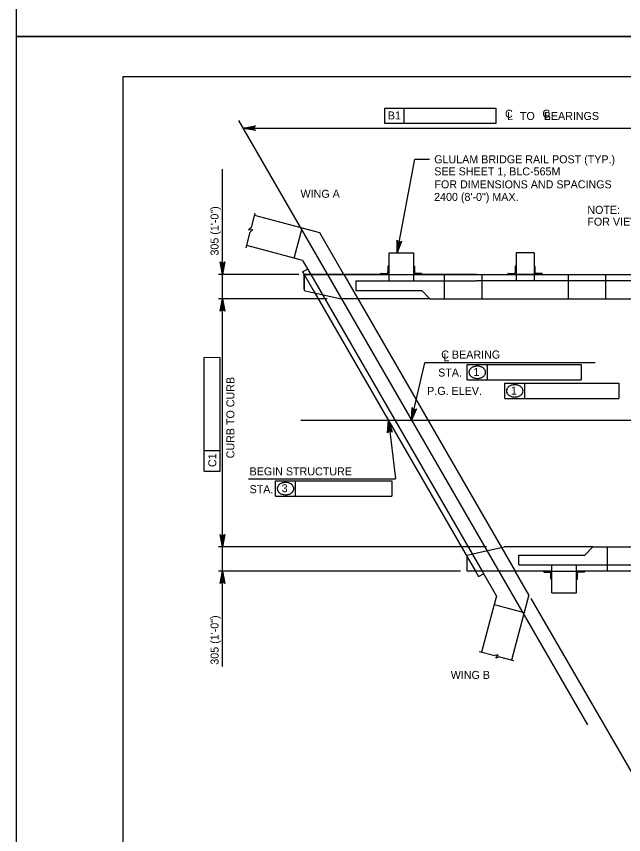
# Model space of a CAD drawing. Extents: x 638175 to 640495, y 294277 to 298435.
# Drawn here: x 638435.5 to 638663, y 296948.4 to 297255 of the extents above; entities that cross this region are included whole.
import ezdxf

# ---------------------------------------------------------------- set-up
doc = ezdxf.new("R2010")
doc.units = 0
for name, color, linetype in [('2', 7, 'Continuous'), ('3', 7, 'Continuous'), ('4', 7, 'Continuous'), ('PLT-BNDY', 7, 'Continuous')]:
    doc.layers.add(name, color=color, linetype=linetype)

msp = doc.modelspace()

# ---------------------------------------------------------------- linework, layer by layer
at = {"layer": '2'}
for p, q in [((638475.46, 296668.46), (638475.46, 297232.46)), ((638475.46, 297232.46), (639261.46, 297232.46)), ((638549.18, 297173.84), (638524.78, 297180.38)), ((638539.56, 297164.37), (638542.57, 297175.61)), ((638558.17, 297158.27), (638549.18, 297173.84)), ((638539.56, 297164.37), (638521.77, 297169.14)), ((638575.02, 297166.36), (638584.25, 297166.36)), ((638575.02, 297166.36), (638575.02, 297155.88)), ((638584.25, 297166.36), (638584.25, 297155.88)), ((638629.41, 297166.36), (638622.68, 297166.36)), ((638629.41, 297166.36), (638622.68, 297166.36)), ((638622.68, 297166.36), (638622.68, 297155.88)), ((638629.41, 297166.36), (638629.41, 297155.88)), ((638542.71, 297163.52), (638539.56, 297164.37)), ((638542.71, 297163.52), (638545.74, 297158.27)), ((638542.73, 297159.22), (638544.58, 297160.29)), ((638542.73, 297159.22), (638544.58, 297160.29)), ((638574.65, 297161.18), (638574.65, 297159)), ((638574.83, 297161.36), (638575.02, 297161.36)), ((638575.02, 297161.36), (638575.02, 297158.27)), ((638584.43, 297161.36), (638584.25, 297161.36)), ((638584.25, 297161.36), (638584.25, 297158.27)), ((638584.62, 297161.18), (638584.62, 297159)), ((638622.32, 297161.18), (638622.32, 297159)), ((638622.5, 297161.36), (638622.68, 297161.36)), ((638622.68, 297161.36), (638622.68, 297158.27)), ((638629.59, 297161.36), (638629.41, 297161.36)), ((638629.41, 297161.36), (638629.41, 297158.27)), ((638629.77, 297161.18), (638629.77, 297159)), ((638542.73, 297159.22), (638543.27, 297158.29)), ((638543.27, 297158.27), (638755.15, 297158.27)), ((638543.27, 297152.89), (638543.27, 297158.27)), ((638543.27, 297158.27), (638543.27, 297152.24)), ((638575.02, 297158.27), (638543.27, 297158.27)), ((638543.28, 297158.27), (638547.02, 297151.79)), ((638545.74, 297158.27), (638609.93, 297047.1)), ((638558.17, 297158.27), (638622.36, 297047.1)), ((638571.92, 297158.45), (638571.92, 297158.27)), ((638575.02, 297158.27), (638571.92, 297158.27)), ((638572.11, 297158.63), (638574.29, 297158.63)), ((638575.02, 297158.27), (638584.25, 297158.27)), ((638584.25, 297158.27), (638587.34, 297158.27)), ((638607.96, 297158.27), (638584.25, 297158.27)), ((638587.16, 297158.63), (638584.98, 297158.63)), ((638587.34, 297158.45), (638587.34, 297158.27)), ((638595.8, 297158.27), (638595.8, 297149.15)), ((638608.04, 297158.27), (638755.13, 297158.27)), ((638609.87, 297158.27), (638609.87, 297149.15)), ((638619.59, 297158.45), (638619.59, 297158.27)), ((638622.68, 297158.27), (638619.59, 297158.27)), ((638619.77, 297158.63), (638621.95, 297158.63)), ((638630.66, 297158.27), (638621.42, 297158.27)), ((638629.41, 297158.27), (638622.68, 297158.27)), ((638629.41, 297158.27), (638632.5, 297158.27)), ((638632.32, 297158.63), (638630.13, 297158.63)), ((638632.5, 297158.45), (638632.5, 297158.27)), ((638642.21, 297158.27), (638642.21, 297149.15)), ((638656.24, 297158.27), (638656.24, 297149.15)), ((638562.69, 297155.88), (638607.87, 297155.88)), ((638562.69, 297155.88), (638562.69, 297152.24)), ((638735.71, 297155.88), (638607.87, 297155.88)), ((638543.27, 297152.24), (638545.44, 297151.76)), ((638545.44, 297151.76), (638557.12, 297149.15)), ((638547.03, 297151.77), (638604.35, 297052.5)), ((638562.69, 297152.24), (638587.33, 297152.24)), ((638590.42, 297149.15), (638587.33, 297152.24)), ((638590.42, 297149.15), (638557.12, 297149.15)), ((638590.42, 297149.15), (638606.58, 297149.15)), ((638590.42, 297149.15), (638741.28, 297149.15)), ((638606.53, 297053.61), (638618.21, 297056.22)), ((638651.51, 297056.22), (638618.21, 297056.22)), ((638651.51, 297056.22), (638648.42, 297053.13)), ((638651.51, 297056.22), (638667.67, 297056.22)), ((638651.51, 297056.22), (638802.37, 297056.22)), ((638656.89, 297047.1), (638656.89, 297056.22)), ((638604.36, 297053.13), (638606.53, 297053.61)), ((638604.36, 297047.1), (638604.36, 297053.13)), ((638623.78, 297049.49), (638623.78, 297053.13)), ((638623.78, 297053.13), (638648.42, 297053.13)), ((638604.36, 297052.48), (638607.47, 297047.1)), ((638636.11, 297047.1), (638604.36, 297047.1)), ((638607.47, 297047.1), (638608.64, 297045.07)), ((638609.93, 297047.1), (638615.33, 297037.75)), ((638627.5, 297038.19), (638622.36, 297047.1)), ((638627.5, 297038.19), (638622.36, 297047.1)), ((638623.78, 297049.49), (638668.96, 297049.49)), ((638633.01, 297046.92), (638633.01, 297047.1)), ((638636.1, 297047.1), (638633.01, 297047.1)), ((638633.2, 297046.73), (638635.38, 297046.73)), ((638636.1, 297044.01), (638636.1, 297047.1)), ((638636.11, 297039.01), (638636.11, 297049.49)), ((638636.11, 297047.1), (638645.34, 297047.1)), ((638645.34, 297039.01), (638645.34, 297049.49)), ((638645.34, 297047.1), (638648.43, 297047.1)), ((638645.34, 297044.01), (638645.34, 297047.1)), ((638669.05, 297047.1), (638645.34, 297047.1)), ((638648.25, 297046.73), (638646.07, 297046.73)), ((638648.43, 297046.92), (638648.43, 297047.1)), ((638608.64, 297045.07), (638610.48, 297046.14)), ((638635.74, 297044.19), (638635.74, 297046.37)), ((638635.92, 297044.01), (638636.1, 297044.01)), ((638645.52, 297044.01), (638645.34, 297044.01)), ((638645.71, 297044.19), (638645.71, 297046.37)), ((638615.33, 297037.75), (638614.48, 297034.59)), ((638627.5, 297038.19), (638620.96, 297013.79)), ((638636.11, 297039.01), (638645.34, 297039.01)), ((638614.48, 297034.59), (638609.72, 297016.8)), ((638614.48, 297034.59), (638625.73, 297031.58))]:
    msp.add_line(p, q, dxfattribs=at)
for centre, radius, start, end in [((638574.83, 297161.18), 0.182, 90, 179.9984), ((638584.43, 297161.18), 0.182, 0.0016, 90), ((638622.5, 297161.18), 0.182, 90, 179.9984), ((638629.59, 297161.18), 0.182, 0.0016, 90), ((638572.11, 297158.45), 0.182, 90, 179.9984), ((638574.29, 297159), 0.364, 270, 359.9984), ((638584.98, 297159), 0.364, 180.0016, 270), ((638587.16, 297158.45), 0.182, 0.0016, 90), ((638619.77, 297158.45), 0.182, 90, 179.9984), ((638621.95, 297159), 0.364, 270, 359.9984), ((638630.13, 297159), 0.364, 180.0016, 270), ((638632.32, 297158.45), 0.182, 0.0016, 90), ((638633.2, 297046.92), 0.182, 180.0016, 270), ((638635.38, 297046.37), 0.364, 0.0016, 90), ((638646.07, 297046.37), 0.364, 90, 179.9984), ((638648.25, 297046.92), 0.182, 270, 359.9984), ((638635.92, 297044.19), 0.182, 180.0016, 270), ((638645.52, 297044.19), 0.182, 270, 359.9984)]:
    msp.add_arc(centre, radius, start, end, dxfattribs=at)
at = {"layer": '3'}
for p, q in [((638518.64, 297215.98), (638649.42, 296989.47)), ((638520.34, 297213.03), (638711.75, 297213.03)), ((638584.73, 297201.51), (638590.25, 297201.51)), ((638523.56, 297175.84), (638524.99, 297181.17)), ((638523.56, 297175.84), (638522.47, 297175.02)), ((638521.53, 297168.26), (638523.1, 297174.1)), ((638522.47, 297175.02), (638524.03, 297175.11)), ((638524.03, 297175.11), (638523.1, 297174.1)), ((638608.85, 297017.03), (638614.68, 297015.47)), ((638616.02, 297015.77), (638614.68, 297015.47)), ((638615.16, 297014.47), (638616.02, 297015.77)), ((638616.42, 297015.01), (638615.16, 297014.47)), ((638616.42, 297015.01), (638621.75, 297013.58))]:
    msp.add_line(p, q, dxfattribs=at)
msp.add_lwpolyline([(638523.29, 297213.52), (638523.29, 297212.54), (638520.34, 297213.03)], close=True, dxfattribs=at)
at = {"layer": '4'}
for p, q in [((638573.56, 297220.57), (638580.79, 297220.57)), ((638573.56, 297214.81), (638573.56, 297220.57)), ((638580.79, 297214.81), (638580.79, 297220.57)), ((638580.79, 297220.57), (638615.09, 297220.57)), ((638615.09, 297220.57), (638615.09, 297214.81)), ((638615.09, 297214.81), (638573.56, 297214.81)), ((638578.11, 297166.36), (638584.73, 297201.51)), ((638512.67, 297011.33), (638512.67, 297197.76)), ((638541.29, 297158.27), (638511.23, 297158.27)), ((638551.87, 297149.15), (638511.23, 297149.15)), ((638511.77, 297127.08), (638505.86, 297127.09)), ((638505.86, 297092.13), (638505.86, 297127.09)), ((638511.77, 297084.56), (638511.77, 297127.08)), ((638583.5, 297103.64), (638588.55, 297125.15)), ((638652.37, 297125.15), (638588.55, 297125.15)), ((638604.38, 297124.53), (638611.95, 297124.53)), ((638604.38, 297118.76), (638604.38, 297124.53)), ((638611.95, 297118.76), (638611.95, 297124.53)), ((638611.95, 297124.53), (638647.14, 297124.53)), ((638647.14, 297124.53), (638647.14, 297118.76)), ((638604.38, 297118.76), (638647.14, 297118.76)), ((638618.42, 297117.56), (638625.99, 297117.56)), ((638618.42, 297111.8), (638618.42, 297117.56)), ((638625.99, 297111.8), (638625.99, 297117.56)), ((638625.99, 297117.56), (638661.18, 297117.56)), ((638661.18, 297117.56), (638661.18, 297111.8)), ((638618.42, 297111.8), (638661.18, 297111.8)), ((638541.99, 297103.64), (638827.01, 297103.64)), ((638574.83, 297103.64), (638577.55, 297081.71)), ((638505.86, 297084.57), (638505.86, 297092.13)), ((638511.77, 297092.13), (638505.86, 297092.13)), ((638505.86, 297084.57), (638511.77, 297084.56)), ((638522.47, 297081.71), (638577.55, 297081.71)), ((638532.53, 297075.18), (638532.53, 297080.94)), ((638532.53, 297080.94), (638540.1, 297080.94)), ((638540.1, 297075.18), (638540.1, 297080.94)), ((638540.1, 297080.94), (638576.11, 297080.94)), ((638576.11, 297080.94), (638576.11, 297075.18)), ((638532.53, 297075.18), (638576.11, 297075.18)), ((638611.65, 297056.22), (638511.23, 297056.22)), ((638601.88, 297047.1), (638511.23, 297047.1)), ((638628.28, 297036.84), (638675.2, 296955.57))]:
    msp.add_line(p, q, dxfattribs=at)
for points in [[(638520.34, 297213.03), (638525, 297213.9), (638524.64, 297213.65), (638524.46, 297213.34), (638524.4, 297213.03), (638524.46, 297212.72), (638524.64, 297212.4), (638525, 297212.16), (638520.34, 297213.03), (638524.64, 297212.4), (638524.46, 297212.72), (638520.34, 297213.03), (638524.4, 297213.03), (638524.46, 297213.34), (638520.34, 297213.03), (638524.64, 297213.65)], [(638578.11, 297166.36), (638578.09, 297171.1), (638578.27, 297170.71), (638578.54, 297170.47), (638578.84, 297170.36), (638579.16, 297170.35), (638579.5, 297170.48), (638579.81, 297170.79), (638578.11, 297166.36), (638579.5, 297170.48), (638579.16, 297170.35), (638578.11, 297166.36), (638578.84, 297170.36), (638578.54, 297170.47), (638578.11, 297166.36), (638578.27, 297170.71)], [(638512.67, 297158.27), (638511.8, 297162.93), (638512.05, 297162.57), (638512.36, 297162.39), (638512.67, 297162.33), (638512.99, 297162.39), (638513.3, 297162.57), (638513.55, 297162.93), (638512.67, 297158.27), (638513.3, 297162.57), (638512.99, 297162.39), (638512.67, 297158.27), (638512.67, 297162.33), (638512.36, 297162.39), (638512.67, 297158.27), (638512.05, 297162.57)], [(638512.67, 297149.15), (638513.55, 297144.49), (638513.3, 297144.85), (638512.99, 297145.03), (638512.67, 297145.09), (638512.36, 297145.03), (638512.05, 297144.85), (638511.8, 297144.49), (638512.67, 297149.15), (638512.05, 297144.85), (638512.36, 297145.03), (638512.67, 297149.15), (638512.67, 297145.09), (638512.99, 297145.03), (638512.67, 297149.15), (638513.3, 297144.85)], [(638583.5, 297103.64), (638583.72, 297108.37), (638583.88, 297107.97), (638584.14, 297107.72), (638584.43, 297107.59), (638584.74, 297107.57), (638585.09, 297107.68), (638585.42, 297107.97), (638583.5, 297103.64), (638585.09, 297107.68), (638584.74, 297107.57), (638583.5, 297103.64), (638584.43, 297107.59), (638584.14, 297107.72), (638583.5, 297103.64), (638583.88, 297107.97)], [(638574.83, 297103.64), (638576.27, 297099.12), (638575.98, 297099.45), (638575.64, 297099.59), (638575.33, 297099.61), (638575.02, 297099.51), (638574.74, 297099.29), (638574.53, 297098.9), (638574.83, 297103.64), (638574.74, 297099.29), (638575.02, 297099.51), (638574.83, 297103.64), (638575.33, 297099.61), (638575.64, 297099.59), (638574.83, 297103.64), (638575.98, 297099.45)], [(638512.67, 297056.22), (638511.8, 297060.88), (638512.05, 297060.52), (638512.36, 297060.34), (638512.67, 297060.28), (638512.99, 297060.34), (638513.3, 297060.52), (638513.55, 297060.88), (638512.67, 297056.22), (638513.3, 297060.52), (638512.99, 297060.34), (638512.67, 297056.22), (638512.67, 297060.28), (638512.36, 297060.34), (638512.67, 297056.22), (638512.05, 297060.52)], [(638512.67, 297047.1), (638513.55, 297042.43), (638513.3, 297042.79), (638512.99, 297042.98), (638512.67, 297043.03), (638512.36, 297042.98), (638512.05, 297042.79), (638511.8, 297042.43), (638512.67, 297047.1), (638512.05, 297042.79), (638512.36, 297042.98), (638512.67, 297047.1), (638512.67, 297043.03), (638512.99, 297042.98), (638512.67, 297047.1), (638513.3, 297042.79)]]:
    msp.add_lwpolyline(points, dxfattribs=at)
for points in [[(638578.15, 297169.36), (638579.12, 297169.18), (638578.11, 297166.36)], [(638512.19, 297161.15), (638513.15, 297161.15), (638512.67, 297158.27)], [(638512.19, 297146.27), (638513.15, 297146.27), (638512.67, 297149.15)], [(638512.19, 297059.1), (638513.15, 297059.1), (638512.67, 297056.22)], [(638512.19, 297044.21), (638513.15, 297044.21), (638512.67, 297047.1)]]:
    msp.add_lwpolyline(points, close=True, dxfattribs=at)
for centre, radius, start, end in [((638607.43, 297121.22), 2.49, 126.3544, 150.6308), ((638607.87, 297120.62), 3.23, 106.9552, 126.3544), ((638608.16, 297119.67), 4.22, 90, 106.9552), ((638608.16, 297119.67), 4.22, 73.0448, 90), ((638608.45, 297120.62), 3.23, 53.6456, 73.0448), ((638608.89, 297121.22), 2.49, 29.3692, 53.6456), ((638606.75, 297121.6), 1.71, 150.6308, 180), ((638606.75, 297121.6), 1.71, 180, 209.3692), ((638607.43, 297121.98), 2.49, 209.3692, 233.6456), ((638608.89, 297121.98), 2.49, 306.3544, 330.6308), ((638609.57, 297121.6), 1.71, 0, 29.3692), ((638609.57, 297121.6), 1.71, 330.6308, 0), ((638607.87, 297122.58), 3.23, 233.6456, 253.0448), ((638608.16, 297123.53), 4.22, 253.0448, 270), ((638608.16, 297123.53), 4.22, 270, 286.9552), ((638608.45, 297122.58), 3.23, 286.9552, 306.3544), ((638620.79, 297114.63), 1.71, 150.6308, 180), ((638620.79, 297114.63), 1.71, 180, 209.3692), ((638621.47, 297114.25), 2.49, 126.3544, 150.6308), ((638621.91, 297113.65), 3.23, 106.9552, 126.3544), ((638622.2, 297112.71), 4.22, 90, 106.9552), ((638622.2, 297112.71), 4.22, 73.0448, 90), ((638622.49, 297113.65), 3.23, 53.6456, 73.0448), ((638622.93, 297114.25), 2.49, 29.3692, 53.6456), ((638623.61, 297114.63), 1.71, 0, 29.3692), ((638623.61, 297114.63), 1.71, 330.6308, 0), ((638621.47, 297115.01), 2.49, 209.3692, 233.6456), ((638621.91, 297115.61), 3.23, 233.6456, 253.0448), ((638622.2, 297116.56), 4.22, 253.0448, 270), ((638622.2, 297116.56), 4.22, 270, 286.9552), ((638622.49, 297115.61), 3.23, 286.9552, 306.3544), ((638622.93, 297115.01), 2.49, 306.3544, 330.6308), ((638536.31, 297076.09), 4.22, 90, 106.9552), ((638536.31, 297076.09), 4.22, 73.0448, 90), ((638534.9, 297078.01), 1.71, 150.6308, 180), ((638534.9, 297078.01), 1.71, 180, 209.3692), ((638535.58, 297077.63), 2.49, 126.3544, 150.6308), ((638535.58, 297078.39), 2.49, 209.3692, 233.6456), ((638536.02, 297077.03), 3.23, 106.9552, 126.3544), ((638536.6, 297077.03), 3.23, 53.6456, 73.0448), ((638537.04, 297077.63), 2.49, 29.3692, 53.6456), ((638537.04, 297078.39), 2.49, 306.3544, 330.6308), ((638537.71, 297078.01), 1.71, 0, 29.3692), ((638537.71, 297078.01), 1.71, 330.6308, 0), ((638536.02, 297078.99), 3.23, 233.6456, 253.0448), ((638536.31, 297079.94), 4.22, 253.0448, 270), ((638536.31, 297079.94), 4.22, 270, 286.9552), ((638536.6, 297078.99), 3.23, 286.9552, 306.3544)]:
    msp.add_arc(centre, radius, start, end, dxfattribs=at)
at = {"layer": 'PLT-BNDY'}
for points in [[(638435.46, 297841.46), (639276.46, 297841.46), (639276.46, 297247.46), (638435.46, 297247.46)], [(638435.46, 297247.46), (639276.46, 297247.46), (639276.46, 296653.46), (638435.46, 296653.46)]]:
    msp.add_lwpolyline(points, close=True, dxfattribs=at)

# ---------------------------------------------------------------- texts
at = {"layer": '2'}
for s, p in [('C', (638618.57, 297216.96)), ('L', (638619.35, 297216.07)), ('C', (638632.54, 297216.99)), ('L', (638633.37, 297216.07))]:
    msp.add_text(s, height=3, dxfattribs=at).set_placement(p)
at = {"layer": '4'}
for s, p in [('B1', (638574.63, 297216.33)), ('TO   BEARINGS', (638624.13, 297216.14)), ('GLULAM BRIDGE RAIL POST (TYP.)', (638592.03, 297199.9)), ('SEE SHEET 1, BLC-565M', (638592.03, 297195.38)), ('FOR DIMENSIONS AND SPACINGS', (638592.1, 297190.53)), ('WING A', (638541.93, 297186.99)), ('2400 (8\'-0") MAX.', (638591.98, 297185.81)), ('NOTE:', (638649.4, 297180.97)), ('FOR VIEW B-B SEE SHEET 4.', (638649.4, 297176.53)), ('C BEARING', (638594.65, 297126.76)), ('L', (638595.48, 297125.7)), ('1', (638606.71, 297120.25)), ('STA.', (638593.49, 297120.01)), ('P.G. ELEV.', (638589.39, 297113.15)), ('1', (638620.75, 297113.28)), ('BEGIN STRUCTURE', (638522.85, 297082.98)), ('STA.', (638522.85, 297076.31)), ('3', (638534.86, 297076.66)), ('WING B', (638598.21, 297006.72))]:
    msp.add_text(s, height=3, dxfattribs=at).set_placement(p)
for s, rotation, p in [('305 (1\'-0")', 90, (638511.21, 297165.34)), ('CURB TO CURB', 90, (638517.15, 297089.35)), ('C1', 89.9382, (638510.37, 297086.09)), ('305 (1\'-0")', 90, (638511.21, 297012.06))]:
    msp.add_text(s, height=3, rotation=rotation, dxfattribs=at).set_placement(p)

doc.saveas('drawing.dxf')
